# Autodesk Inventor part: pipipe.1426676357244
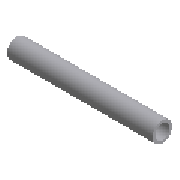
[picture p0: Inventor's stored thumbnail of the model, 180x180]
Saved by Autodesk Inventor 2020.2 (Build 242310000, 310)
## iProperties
Manager: www.cadconsulting.pl
Company: Fabian Stasiak CAD Consulting
NAME: PIPING: JIS G 3458 Pipe
DATA: <meta><inlinegroups number="1" deflen="10"></inlinegroups><connections number="2"></connections><angles><a>3.14159265358979</a></angles></meta>
IsCustomPart: 1
Created: 2014-02
Material: Stal, stopowa
Description: Rura
Document SubType Name: Modeling
Standard: JIS G 3458
Designer: F.Stasiak
Standards Organization: JIS
Language: pl-PL
Size Designation: 40 A x Sch 80 - 100
Categories: <MemberInstance><Categories><Category DisplayName="Rury cienko- i grubościenne" InternalName="4347fa0f-2144-441d-94cd-e3e15c92b736" Mnemonic="TUBEANDPIPE"><Cate
Stock Number: JIS G 3458 Rura 40 A x Sch 80
Density: 7.73 g/cm^3
Appearance: Częściowo polerowana
Catalog Web Link: www.expertbooks.pl
L: 1036,000 mm
PL: 1036,000 mm
Author: F.Stasiak
Subject: Zbiór ćwiczeń. Autodesk Inventor 2020. Kurs Professional
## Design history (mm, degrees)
sketch "Sketch1"
  geometry: C1 r 24.3 at (0, 0); C2 r 19.2 at (0, 0); 1 further point
  constraints: 2 centre point, 2 coincident, 1 concentric
  dimensions: "d0" = 48.6 diameter of C1 (= OD); "d1" = 38.4 diameter of C2 (= OD - 2 x t)
extrude "Extrusion1" new body sketch "Sketch1" distance "d2" = 1036 (= L); taper "d3" = 0 deg
workaxis "Work Axis1"
workpoint "Work Point1"
workaxis "Work Axis2"
workpoint "Work Point2"
body "Solid1"
other parameters: "OD" = 48.6 [user parameter; used in 2 equation terms], "t" = 5.1 [user parameter; used in 1 equation term], "L" = 1036 (= PL) [user parameter; used in 1 equation term], "ID" = 38.4 [user parameter], "PL" = 1036 [user parameter; used in 1 equation term], "Size_Designation" = 12.345 [user parameter]
